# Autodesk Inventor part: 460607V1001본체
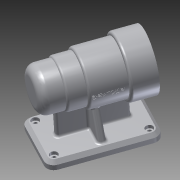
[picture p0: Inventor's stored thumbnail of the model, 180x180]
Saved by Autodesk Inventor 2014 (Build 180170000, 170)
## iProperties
Created: 2016-06
Part Number: 460607V1001본체
Material: 알루미늄 6061
Document SubType Name: Modeling
Designer: SEC
Density: 2.71 g/cm^3
Appearance: 알루미늄 - 평지
Mass: 670.177 g
Surface Area: 650.854 cm^2
Volume: 247.298 cm^3
Author: SEC
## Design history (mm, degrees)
sketch "스케치1"
  geometry: L1 (-56, 0)-(56, 0); L2 (-56, 0)-(-56, 25); L3 (-56, 25)-(-31, 25); L4 (-31, 25)-(-31, 27); L5 (-31, 27)-(-11, 27); L6 (-11, 27)-(-11, 30); L7 (-11, 30)-(28, 30); L8 (28, 30)-(28, 34); L9 (28, 34)-(56, 34); L10 (56, 34)-(56, 0); 2 further points
  constraints: 20 end point, 5 parallel, 4 perpendicular, 1 coincident, 1 horizontal, 1 midpoint
  dimensions: "d0" = 112 distance of L1.start L1.end; "d1" = 25 distance of L2.end L3.end; "d2" = 45 distance from line of L5.end L2; "d3" = 84 distance between parallel lines of L8 L2; "d4" = 50 diameter of L3 L1; "d5" = 54 diameter of L5 L1; "d6" = 60 diameter of L7 L1; "d7" = 68 diameter of L9 L1
revolve "회전1" sketch "스케치1" stored, may be unused: angle "d8" = 90 deg
node "작업 평면1"
sketch "스케치2"
  geometry: L1 (56, 35)-(-56, 35); L2 (-56, 35)-(-56, -35); L3 (-56, -35)-(56, -35); L4 (56, -35)-(56, 35); L5 (56, 35)-(-56, -35); L6 (-56, 35)-(56, -35); 1 further point
  constraints: 12 end point, 2 midpoint, 2 parallel, 1 horizontal, 1 perpendicular
  dimensions: "d10" = 112 distance of L2.end L3.end; "d11" = 70 distance of L1.end L2.end
extrude "돌출1" join sketch "스케치2" distance "d12" = 10; taper "d13" = 0 deg
sketch "스케치3"
  geometry: L1 (-36, 4)-(36, 4); L2 (36, 4)-(36, -4); L3 (36, -4)-(-36, -4); L4 (-36, -4)-(-36, 4); L5 (-36, 4)-(36, -4); L6 (36, 4)-(-36, -4); 1 further point
  constraints: 12 end point, 2 midpoint, 2 parallel, 1 horizontal, 1 perpendicular
  dimensions: "d14" = 8 distance of L1.end L2.end; "d15" = 72 distance of L1.start L1.end
extrude "돌출2" join sketch "스케치3" stored distance "d16" = 10; taper "d17" = 0 deg
sketch "스케치4"
  geometry: L1 (35, -60)-(-35, -60) reference; L2 (15.509, -25.68)-(28, -60); L3 (35, -70)-(35, -60) reference; A1 r 30 centre (0, 0) between (4, -29.732) and (-4, -29.732) reference; 1 further point
  constraints: 2 end point, 1 point on circle, 1 point on line
  dimensions: "d18" = 7 distance from line of L3 L2.end; "d19" = 110 deg angle of L1 L2
feature "리브1" sketch "스케치4" dims "d20" = 1, "d21" = 8, "d22" = 0, "d23" = 0, "d24" = 1, "d25" = 1
sketch "스케치5"
  geometry: C1 r 34 at (0, 0) reference; C2 r 21 at (0, 0)
  constraints: 1 centre point, 1 coincident
  dimensions: "d26" = 42 diameter of C2
extrude "돌출3" cut sketch "스케치5" distance "d27" = 15; taper "d28" = 0 deg
sketch "스케치6"
  geometry: C1 r 21 at (0, 0) reference; C2 r 24 at (0, 0)
  constraints: 1 centre point, 1 coincident
  dimensions: "d29" = 48 diameter of C2
extrude "돌출4" cut sketch "스케치6" distance "d30" = 54; taper "d31" = 0 deg
sketch "스케치9"
  geometry: C1 r 24 at (0, 0) reference; C2 r 21 at (0, 0)
  constraints: 1 centre point, 1 coincident
  dimensions: "d34" = 42 diameter of C2
extrude "돌출6" cut sketch "스케치9" distance "d35" = 12; taper "d36" = 0 deg
sketch "스케치10"
  geometry: C1 r 21 at (0, 0) reference; C2 r 17.5 at (0, 0)
  constraints: 1 centre point, 1 coincident
  dimensions: "d37" = 35 diameter of C2
extrude "돌출7" cut sketch "스케치10" distance "d38" = 18; taper "d39" = 0 deg
sketch "스케치11"
  geometry: C1 r 17.5 at (0, 0) reference; C2 r 16 at (0, 0)
  constraints: 1 centre point, 1 coincident
  dimensions: "d40" = 32 diameter of C2
extrude "돌출8" cut sketch "스케치11" distance "d41" = 4; taper "d42" = 0 deg
sketch "스케치12"
  geometry: C1 r 16 at (0, 0) reference; C2 r 10.5 at (0, 0)
  constraints: 1 centre point, 1 coincident
  dimensions: "d43" = 21 diameter of C2
extrude "돌출9" cut sketch "스케치12" distance "d44" = 3; taper "d45" = 0 deg
fillet "모깎기1" dims "d46" = 3
sketch "스케치13"
  geometry: L1 (56, 35)-(-56, 35) reference; L2 (-56, 35)-(-56, -35) reference; L3 (-56, -35)-(56, -35) reference; L4 (56, -35)-(56, 35) reference; L5 (-46, 25)-(46, 25); L6 (46, 25)-(46, -25); L7 (46, -25)-(-46, -25); L8 (-46, -25)-(-46, 25); 5 further points
  constraints: 8 end point, 4 coincident, 3 other
  dimensions: "d47" = 92 distance of L5.start L5.end; "d48" = 50 distance of L7.end L5.start (derived)
hole "구멍1" sketch "스케치13" at (-46, 25), (46, 25), (46, -25), (-46, -25) diameter "d49" = 5; stored, may be unused: countersink angle "d53" = 90 deg, drill point angle "d55" = 118 deg; dims "d50" = 6, "d51" = 9, "d52" = 4, "d54" = 10
fillet "모깎기2" dims "d56" = 10
fillet "모깎기3" dims "d57" = 10
sketch "스케치14"
  geometry: C1 r 21 at (0, 0) reference; 1 further point
  constraints: 1 horizontal alignment
  dimensions: "d58" = 26 distance of C1.centre point (26, 0)
hole "구멍2" sketch "스케치14" at (26, 0) diameter "d59" = 3.242; stored, may be unused: countersink angle "d63" = 90 deg, drill point angle "d65" = 118 deg; dims "d60" = 8, "d61" = 9, "d62" = 4, "d64" = 11
node "작업 평면2"
sketch "스케치15"
  geometry: L1 (47.5, -34)-(47.5, 34) reference; 2 further points
  constraints: 1 horizontal alignment, 1 other
  dimensions: "d69" = 48 distance from line of point (-0.5, 0) L1
feature "엠보싱1" sketch "스케치15" dims "d0" = 112, "d13" = 0, "d70" = 0.5, "d71" = 0
chamfer "모따기1" distance "d72" = 4; stored, may be unused: second distance "d73" = 2, angle "d74" = 45 deg
fillet "모깎기4" dims "d75" = 0.3
fillet "모깎기5" dims "d76" = 0.3
fillet "모깎기6" dims "d77" = 3
fillet "모깎기7" dims "d78" = 3
fillet "모깎기8" dims "d79" = 3
fillet "모깎기9" dims "d80" = 3
fillet "모깎기18" dims "d89" = 3
fillet "모깎기19" dims "d90" = 3
fillet "모깎기20" dims "d91" = 3
fillet "모깎기21" dims "d92" = 3
node "솔리드1"
mirror "대칭1"
pattern_circular "원형 패턴1" dims angle "d67" = 360 deg
